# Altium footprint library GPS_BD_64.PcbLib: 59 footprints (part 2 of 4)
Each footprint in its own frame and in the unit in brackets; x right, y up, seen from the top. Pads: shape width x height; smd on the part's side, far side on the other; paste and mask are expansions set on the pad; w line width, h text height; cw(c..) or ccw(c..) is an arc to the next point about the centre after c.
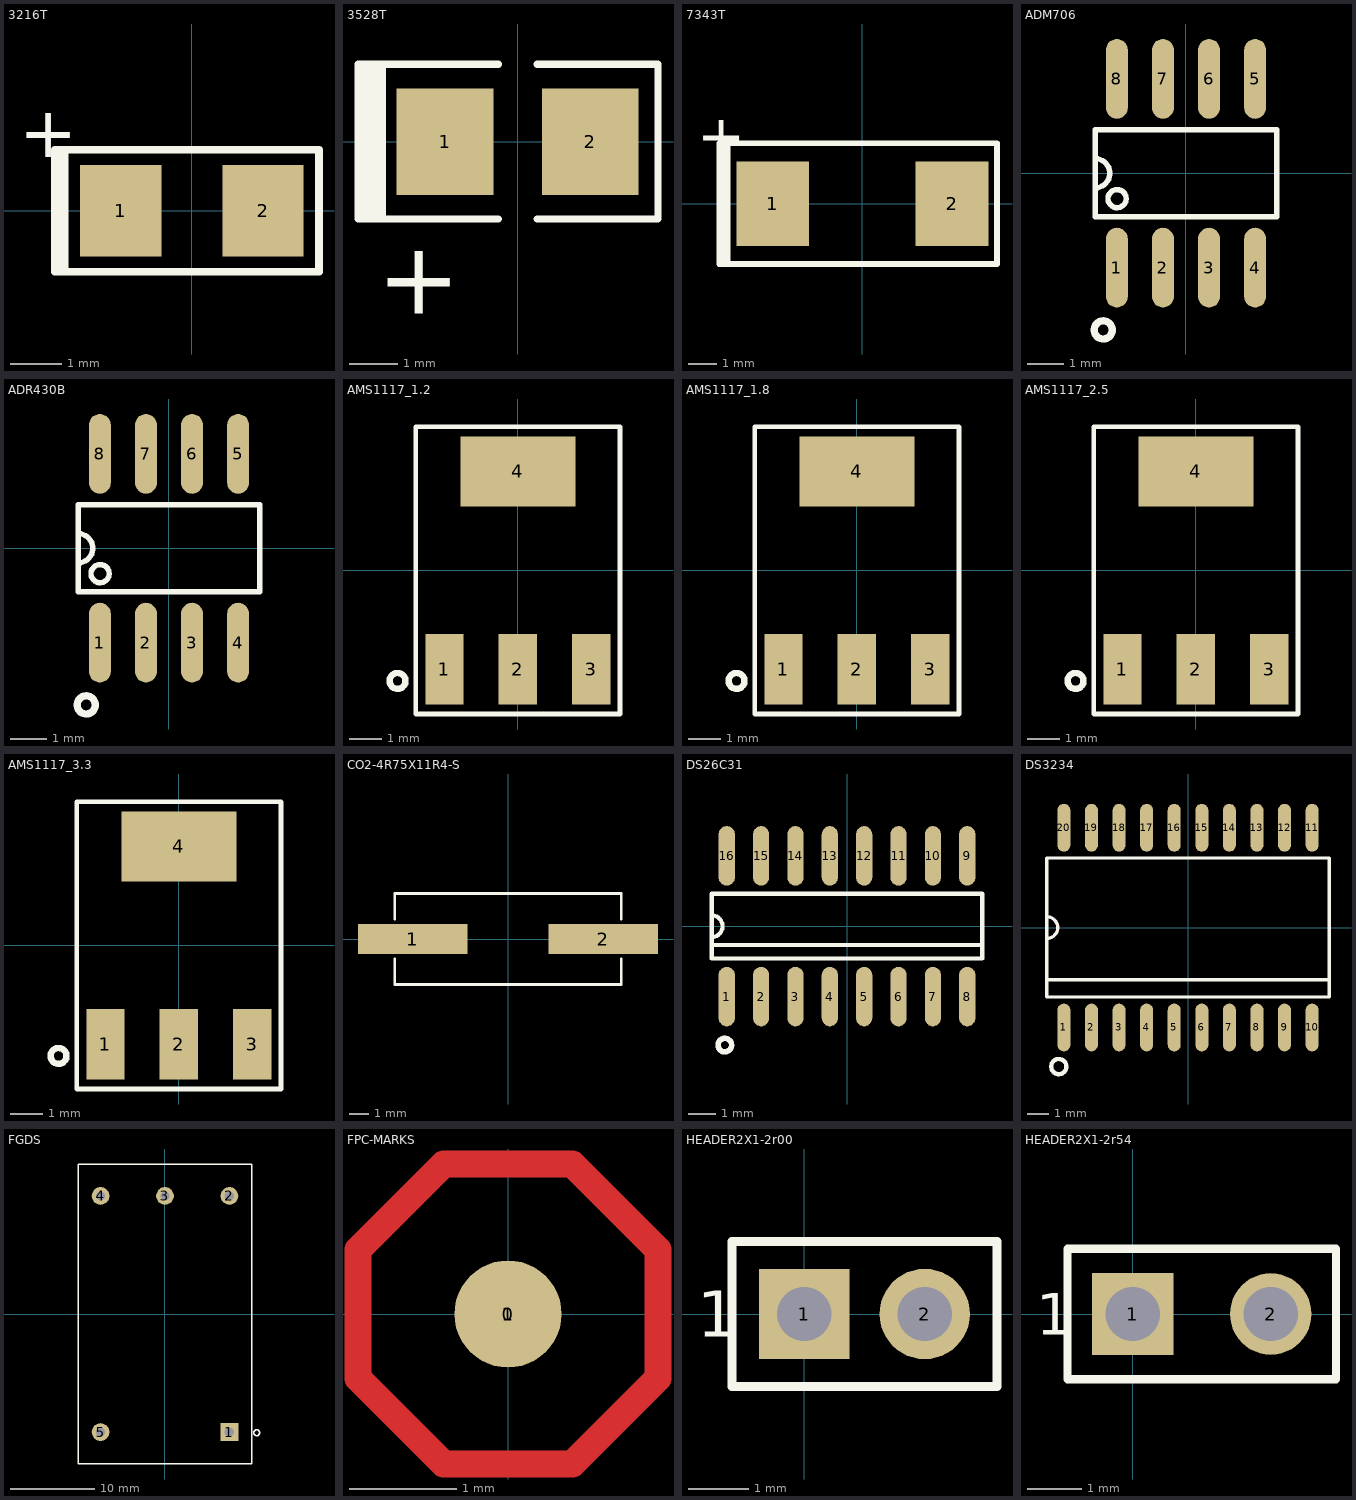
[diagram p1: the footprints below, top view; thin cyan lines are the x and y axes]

## 3216T [mm]
height 11
pads (2):
  rect 1.6x1.8 smd: 1(-1.4,0) 2(1.4,0)
Top Overlay:
  lines w0.15: -2.6,-1.2 -2.6,1.2 ; -2.5,-1.2 1.2,-1.2 2.5,-1.2 2.5,1.2 -1.1,1.2 -2.5,1.2 ; -2.5,-1.2 -2.5,1.2 ; -2.5,-1.2 -2.7,-1.2 -2.7,1.2 -2.5,1.2
  text "+" at -3.4,1.05 h1

## 3528T [mm]
height 1.45
pads (2):
  rect 2x2.2 smd: 1(-1.5,0) 2(1.5,0)
Top Overlay:
  lines w0.15: -3,-1.4 -3,1.4 -3.1,1.4 -3.1,-1.5 -2.9,-1.5 -2.9,1.5 -3.2,1.5 -3.2,-1.6 -2.8,-1.6 -2.8,1.6 ; -0.4,-1.6 -3.3,-1.6 -3.3,1.6 -0.4,1.6 ; 0.4,-1.6 2.9,-1.6 2.9,1.6 0.4,1.6
  text "+" at -2.898,-3.555 h1.5

## 7343T [mm]
height 1.45
pads (2):
  rect 2.6x3 smd: 1(-3.2,0) 2(3.2,0)
Top Overlay:
  lines w0.2: -4.95,-2.15 -4.95,2.15 ; -4.8,-2.15 -4.8,2.15 ; -4.8,-2.15 -4.1,-2.15 4.8,-2.15 4.8,2.15 -4.8,2.15 ; -4.8,-2.15 -5.1,-2.15 -5.1,2.15 -4.8,2.15
  text "+" at -5.9,1.7 h1.5

## ADM706 [mm]
height 1.45
pads (8):
  oval 0.6x2.2 smd: 1(-1.905,-2.6) 2(-0.635,-2.6) 3(0.635,-2.6) 4(1.905,-2.6) 5(1.905,2.6) 6(0.635,2.6) 7(-0.635,2.6) 8(-1.905,2.6)
Top Overlay:
  circle w0.2: c-2.282,-4.318 r0.25
  circle w0.15: c-1.9,-0.7 r0.25
  lines w0.15: -2.5,-0.4 ccw(c-2.5,0) -2.5,0.4 ; -2.5,-1.2 -2.5,1.2 2.5,1.2 2.5,-1.2 -2.5,-1.2

## ADR430B [mm]
height 1.45
pads (8):
  oval 0.6x2.2 smd: 1(-1.905,-2.6) 2(-0.635,-2.6) 3(0.635,-2.6) 4(1.905,-2.6) 5(1.905,2.6) 6(0.635,2.6) 7(-0.635,2.6) 8(-1.905,2.6)
Top Overlay:
  circle w0.15: c-1.9,-0.7 r0.25
  circle w0.2: c-2.282,-4.318 r0.25
  lines w0.15: -2.5,-0.4 ccw(c-2.5,0) -2.5,0.4 ; -2.5,-1.2 2.5,-1.2 2.5,1.2 -2.5,1.2 -2.5,-1.2

## AMS1117_1.2 [mm]
height 1.45
pads (4):
  rect 1.2x2.2 smd: 1(-2.3,-3.1) 2(0,-3.1) 3(2.3,-3.1)
  rect 3.6x2.2 smd: 4(0,3.1)
Top Overlay:
  circle w0.2: c-3.77,-3.464 r0.25
  lines w0.15: -3.2,-4.5 -3.2,4.5 3.2,4.5 3.2,-4.5 -3,-4.5 -3.2,-4.5

## AMS1117_1.8 [mm]
height 1.45
pads (4):
  rect 1.2x2.2 smd: 1(-2.3,-3.1) 2(0,-3.1) 3(2.3,-3.1)
  rect 3.6x2.2 smd: 4(0,3.1)
Top Overlay:
  circle w0.2: c-3.77,-3.464 r0.25
  lines w0.15: -3.2,-4.5 -3.2,4.5 3.2,4.5 3.2,-4.5 -3,-4.5 -3.2,-4.5

## AMS1117_2.5 [mm]
height 1.45
pads (4):
  rect 1.2x2.2 smd: 1(-2.3,-3.1) 2(0,-3.1) 3(2.3,-3.1)
  rect 3.6x2.2 smd: 4(0,3.1)
Top Overlay:
  circle w0.2: c-3.77,-3.464 r0.25
  lines w0.15: -3.2,-4.5 -3.2,4.5 3.2,4.5 3.2,-4.5 -3,-4.5 -3.2,-4.5

## AMS1117_3.3 [mm]
height 11
pads (4):
  rect 1.2x2.2 smd: 1(-2.3,-3.1) 2(0,-3.1) 3(2.3,-3.1)
  rect 3.6x2.2 smd: 4(0,3.1)
Top Overlay:
  circle w0.2: c-3.77,-3.464 r0.25
  lines w0.15: -3.2,-4.5 -3,-4.5 3.2,-4.5 3.2,4.5 -3.2,4.5 -3.2,-4.5

## CO2-4R75X11R4-S [mm]
height 11
pads (2):
  rect 5.5x1.5 smd: 1(-4.8,0) 2(4.8,0)
Top Overlay:
  lines w0.15: -5.7,-1 -5.7,-2.3 5.7,-2.3 5.7,-1 ; -5.7,1 -5.7,2.3 5.7,2.3 5.7,1

## DS26C31 [mm]
height 1.45
pads (16):
  oval 0.6x2.2 smd: 1(-4.445,-2.6) 2(-3.175,-2.6) 3(-1.905,-2.6) 4(-0.635,-2.6) 5(0.635,-2.6) 6(1.905,-2.6) 7(3.175,-2.6) 8(4.445,-2.6) 9(4.445,2.6) 10(3.175,2.6) 11(1.905,2.6) 12(0.635,2.6) 13(-0.635,2.6) 14(-1.905,2.6) 15(-3.175,2.6) 16(-4.445,2.6)
Top Overlay:
  circle w0.2: c-4.517,-4.394 r0.25
  lines w0.15: -5,-0.7 5,-0.7 ; -5,-0.4 ccw(c-5,0) -5,0.4 ; -5,-1.2 5,-1.2 5,1.2 -5,1.2 -5,-1.2

## DS3234 [mm]
height 1.45
pads (20):
  oval 0.6x2.2 smd: 1(-5.715,-4.6) 2(-4.445,-4.6) 3(-3.175,-4.6) 4(-1.905,-4.6) 5(-0.635,-4.6) 6(0.635,-4.6) 7(1.905,-4.6) 8(3.175,-4.6) 9(4.445,-4.6) 10(5.715,-4.6) 11(5.715,4.6) 12(4.445,4.6) 13(3.175,4.6) 14(1.905,4.6) 15(0.635,4.6) 16(-0.635,4.6) 17(-1.905,4.6) 18(-3.175,4.6) 19(-4.445,4.6) 20(-5.715,4.6)
Top Overlay:
  circle w0.2: c-5.95,-6.4 r0.35
  lines w0.15: -6.5,-2.4 6.5,-2.4 ; -6.5,-0.5 ccw(c-6.5,0) -6.5,0.5 ; -6.5,-3.2 6.5,-3.2 6.5,3.2 -6.5,3.2 -6.5,-3.2

## FGDS [mm]
height 1.45
pads (5):
  rect 2.1x2.1 hole 1.1: 1(7.62,-13.97)
  round 2.1 hole 1.1: 2(7.62,13.97) 3(0,13.97) 4(-7.62,13.97) 5(-7.62,-13.97)
Top Overlay:
  circle w0.2: c10.85,-14.05 r0.35
  lines w0.15: -10.25,-17.75 10.25,-17.75 10.25,17.75 -10.25,17.75 -10.25,-17.75

## FPC-MARKS [mm]
pads (2):
  round 2 on Top Solder: 0(0,0)
  round 1 smd: 1(0,0)
Top Layer:
  lines w0.254: -1.4,-0.6 -0.6,-1.4 -0.4,-1.4 0.4,-1.4 0.6,-1.4 1.4,-0.6 1.4,0.6 0.6,1.4 -0.6,1.4 -1.4,0.6 -1.4,-0.6

## HEADER2X1-2r00 [mm]
height 1.45
pads (2):
  rect 1.5x1.5 hole 0.9: 1(0,0)
  round 1.5 hole 0.9: 2(2,0)
Top Overlay:
  lines w0.15: -1.2,-1.2 -1.2,1.2 3.2,1.2 3.2,-1.2 -1.2,-1.2
  text "1" at -1.778,-0.381 h0.76

## HEADER2X1-2r54 [mm]
height 1.45
pads (2):
  rect 1.5x1.5 hole 1: 1(0,0)
  round 1.5 hole 1: 2(2.54,0)
Top Overlay:
  lines w0.15: -1.2,-1.2 3.74,-1.2 3.74,1.2 -1.2,1.2 -1.2,-1.2
  text "1" at -1.778,-0.381 h0.76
